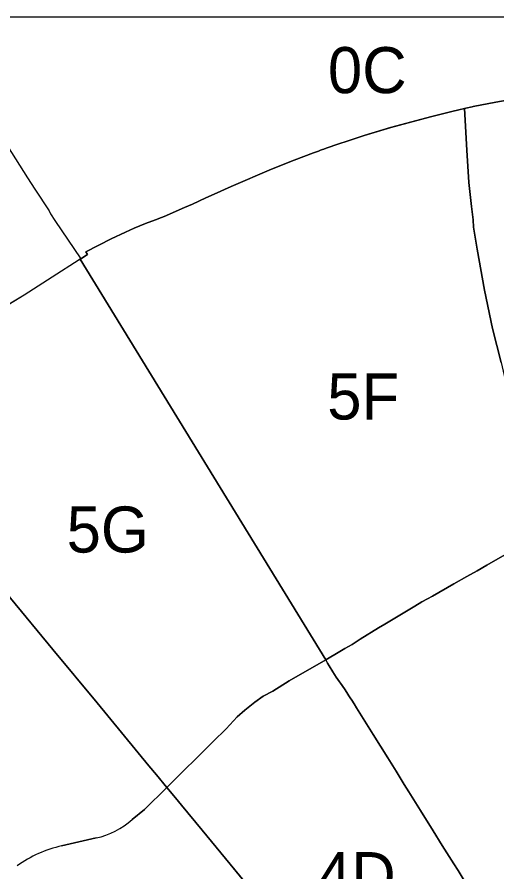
# Model space of a CAD drawing. Extents: x 152750 to 166250, y 378996 to 390000.
# Drawn here: x 157492 to 159576, y 386288 to 390000 of the extents above; entities that cross this region are included whole.
import ezdxf

# ---------------------------------------------------------------- set-up
doc = ezdxf.new("R2010")
doc.units = 0
doc.layers.add('BLT_Nummers', color=7, linetype='Continuous')
doc.layers.add('BLT_Shapes', color=7, linetype='Continuous')

msp = doc.modelspace()

# ---------------------------------------------------------------- linework, layer by layer
at = {"layer": 'BLT_Shapes'}
for p, q in [((163502.8, 390000), (157101, 390000)), ((159473.5, 389611.2), (159571.7, 389630.9)), ((159571.7, 389630.9), (159473.5, 389611.2)), ((159571.7, 389630.9), (159670.9, 389648.8)), ((159670.9, 389648.8), (159571.7, 389630.9)), ((159435.7, 389602.7), (159410.2, 389597)), ((159441.2, 389603.9), (159435.7, 389602.7)), ((159441.2, 389603.9), (159468.8, 389610.2)), ((159468.8, 389610.2), (159441.2, 389603.9)), ((159468.8, 389610.2), (159473.5, 389611.2)), ((159473.5, 389611.2), (159468.8, 389610.2)), ((158834.6, 389430.4), (158824.5, 389426.8)), ((158695.6, 389379.1), (158597.2, 389339.9)), ((158597.2, 389339.9), (158422.3, 389264.6)), ((159455, 389268.9), (159454.2, 389281.4)), ((159465.3, 389176.8), (159455, 389268.9)), ((158312.2, 389214.6), (158253.9, 389188.2)), ((158219.7, 389173.3), (158131.1, 389134.8)), ((158253.9, 389188.2), (158219.7, 389173.3)), ((159473.4, 389120), (159465.3, 389176.8)), ((159473.9, 389088.3), (159473.4, 389120)), ((159489.7, 388991.7), (159473.9, 389088.3)), ((157765.5, 388948.2), (157741.5, 388932.9)), ((157768.1, 388949.9), (157765.5, 388948.2)), ((157765.5, 388948.2), (158832.4, 387209.5)), ((158832.4, 387209.5), (157765.5, 388948.2)), ((157793.5, 388966.1), (157768.1, 388949.9)), ((157521.8, 388792.8), (157405.1, 388721.9)), ((159532.8, 387620.6), (159610.8, 387665.5)), ((159219, 387441.9), (159250.2, 387460.1)), ((159250.2, 387460.1), (159274.2, 387473.7)), ((158946.8, 387276.1), (158982.2, 387298)), ((158674.2, 387117.6), (158832.4, 387209.5)), ((158832.4, 387209.5), (158840.8, 387194.7)), ((158602.5, 387073.4), (158674.2, 387117.6)), ((158884.5, 387123.4), (158903.3, 387098.1)), ((158928.7, 387059.6), (158933, 387052.1)), ((158933, 387052.1), (158938.8, 387043.7)), ((158481.7, 386989.7), (158524.8, 387025.5)), ((158938.8, 387043.7), (158945.3, 387033.3)), ((158448.3, 386961), (158481.7, 386989.7)), ((158400.4, 386909.6), (158448.3, 386961)), ((158343.1, 386854.5), (158400.4, 386909.6)), ((159038, 386885.3), (159101.8, 386783.2)), ((158142.3, 386654.8), (158343.1, 386854.5)), ((159101.8, 386783.2), (159138.1, 386725)), ((158045.2, 386558.7), (158142.3, 386654.8)), ((158142.3, 386654.8), (158180.1, 386609.2)), ((158180.1, 386609.2), (158142.3, 386654.8)), ((158180.1, 386609.2), (158206.4, 386577.5)), ((158206.4, 386577.5), (158180.1, 386609.2)), ((158296.1, 386469.4), (158206.4, 386577.5)), ((157991.4, 386515.6), (158045.2, 386558.7)), ((159244.4, 386554.7), (159299.6, 386466.5)), ((158417.7, 386321.3), (158296.1, 386469.4)), ((157834.8, 386435.5), (157685.4, 386400.8)), ((157685.4, 386400.8), (157834.8, 386435.5)), ((158559.6, 386149.1), (158417.7, 386321.3))]:
    msp.add_line(p, q, dxfattribs=at)
for points in [[(157101, 390000), (157206, 389831.1), (157337.3, 389621), (157449.6, 389439.9), (157536.9, 389302.4), (157569, 389253.3), (157631.4, 389159.1), (157636.9, 389146.1), (157655.3, 389116.9), (157768.1, 388949.9)], [(157768.1, 388949.9), (157793.5, 388966.1), (157798, 388969), (157790.9, 388980.5), (157899.8, 389036.8), (157962.2, 389065.7), (157981.3, 389074.6), (158000, 389083.3), (158049.7, 389103.9), (158093.6, 389119.1), (158118.7, 389129.4), (158131.1, 389134.8), (158219.7, 389173.3), (158253.9, 389188.2), (158312.2, 389214.6), (158348.4, 389231.1), (158422.3, 389264.6), (158597.2, 389339.9), (158695.6, 389379.1), (158779, 389410.6), (158800.8, 389418.4), (158810.3, 389421.8), (158818.1, 389424.5), (158824.5, 389426.8), (158834.6, 389430.4), (158846.8, 389434.7), (158877.1, 389445.5), (158939.1, 389465.8), (159000, 389485.8), (159115.2, 389520.7), (159287.7, 389567.6), (159379.7, 389590.1), (159410.2, 389597), (159441.2, 389603.9)], [(159410.2, 389597), (159379.7, 389590.1), (159287.7, 389567.6), (159114.2, 389520.4), (159000, 389485.8), (158939.1, 389465.8)], [(159435.7, 389602.7), (159445.7, 389422.8), (159454.2, 389281.4), (159455, 389268.9), (159465.3, 389176.8), (159473.4, 389120), (159473.9, 389088.3), (159489.7, 388991.7), (159522.2, 388814.1), (159556.9, 388647.5), (159594.9, 388500.2), (159612.6, 388424.8), (159641, 388307.4), (159654.7, 388247.3), (159661.5, 388218), (159672.4, 388174.9)], [(159454.2, 389281.4), (159445.7, 389422.8), (159435.7, 389602.7)], [(158939.1, 389465.8), (158877.1, 389445.5), (158846.8, 389434.7), (158834.6, 389430.4)], [(157449.6, 389439.9), (157536.9, 389302.4), (157569, 389253.3), (157631.4, 389159.1), (157636.9, 389146.1), (157655.3, 389116.9), (157768.1, 388949.9), (157741.5, 388932.9), (157663.7, 388883.3), (157521.8, 388792.8), (157405.1, 388721.9)], [(158824.5, 389426.8), (158818.1, 389424.5), (158810.3, 389421.8), (158800.8, 389418.4), (158779, 389410.6), (158695.6, 389379.1)], [(158422.3, 389264.6), (158348.4, 389231.1), (158312.2, 389214.6)], [(158131.1, 389134.8), (158118.7, 389129.4), (158093.6, 389119.1), (158049.7, 389103.9), (158000, 389083.3), (157981.3, 389074.6), (157962.2, 389065.7), (157899.8, 389036.8), (157790.9, 388980.5), (157798, 388969), (157793.5, 388966.1)], [(159594.9, 388500.2), (159556.9, 388647.5), (159522.2, 388814.1), (159489.7, 388991.7)], [(157741.5, 388932.9), (157663.7, 388883.3), (157521.8, 388792.8)], [(156751.8, 388357.8), (156831.4, 388247.5), (156937.4, 388116.5), (157111.7, 387900.3), (157296.6, 387677.3), (157336.2, 387630), (157462.8, 387477), (157647.5, 387253.7), (157839.6, 387022), (158064.5, 386749), (158097.1, 386709.1), (158142.3, 386654.8)], [(159792.8, 387771.2), (159770, 387757.1), (159717.4, 387727.2), (159645.6, 387685.3), (159610.8, 387665.5), (159532.8, 387620.6), (159489.9, 387595.9), (159445.1, 387570.3), (159389.6, 387538.7), (159297, 387485.8), (159274.2, 387473.7), (159250.2, 387460.1), (159219, 387441.9), (159089.4, 387364.2), (159062, 387347.3), (158982.2, 387298), (158946.8, 387276.1), (158916.2, 387258.2), (158893.9, 387244.6), (158832.4, 387209.5)], [(157647.5, 387253.7), (157462.8, 387477), (157336.2, 387630), (157296.6, 387677.3)], [(159389.6, 387538.7), (159445.1, 387570.3), (159489.9, 387595.9), (159532.8, 387620.6)], [(159274.2, 387473.7), (159297, 387485.8), (159389.6, 387538.7)], [(158982.2, 387298), (159062, 387347.3), (159089.4, 387364.2), (159219, 387441.9)], [(158832.4, 387209.5), (158893.9, 387244.6), (158916.2, 387258.2), (158946.8, 387276.1)], [(158142.3, 386654.8), (158097.1, 386709.1), (158064.5, 386749), (157839.6, 387022), (157647.5, 387253.7)], [(158832.4, 387209.5), (158674.2, 387117.6), (158602.5, 387073.4), (158560.6, 387050.7), (158524.8, 387025.5), (158481.7, 386989.7), (158448.3, 386961), (158400.4, 386909.6), (158343.1, 386854.5), (158142.3, 386654.8)], [(159442.8, 386236.3), (159407.4, 386293.5), (159389.6, 386322.5), (159339, 386403.1), (159299.6, 386466.5), (159244.4, 386554.7), (159193.6, 386636), (159173.8, 386667.5), (159138.1, 386725), (159101.8, 386783.2), (159038, 386885.3), (158966.6, 386999.9), (158955.3, 387017.4), (158945.3, 387033.3), (158938.8, 387043.7), (158933, 387052.1), (158928.7, 387059.6), (158916.4, 387078.4), (158903.3, 387098.1), (158884.5, 387123.4), (158877.7, 387134.1), (158863.1, 387157.1), (158846.9, 387183.1), (158840.8, 387194.7), (158832.4, 387209.5)], [(158840.8, 387194.7), (158846.9, 387183.1), (158863.1, 387157.1), (158877.7, 387134.1), (158884.5, 387123.4)], [(158903.3, 387098.1), (158916.4, 387078.4), (158928.7, 387059.6)], [(158524.8, 387025.5), (158560.6, 387050.7), (158602.5, 387073.4)], [(158945.3, 387033.3), (158955.3, 387017.4), (158966.6, 386999.9), (159038, 386885.3)], [(159138.1, 386725), (159173.8, 386667.5), (159193.6, 386636), (159244.4, 386554.7)], [(158142.3, 386654.8), (158045.2, 386558.7), (157991.4, 386515.6)], [(158206.4, 386577.5), (158296.1, 386469.4), (158417.7, 386321.3), (158559.6, 386149.1), (158640.6, 386051.2), (158726.9, 385947.1), (158878.9, 385763.5), (159020.3, 385592.2), (159157.3, 385425.3), (159291.1, 385263.1)], [(159299.6, 386466.5), (159339, 386403.1), (159389.6, 386322.5), (159407.4, 386293.5), (159442.8, 386236.3), (159509.8, 386129.4), (159517.9, 386116.7)]]:
    msp.add_lwpolyline(points, dxfattribs=at)
for centre, radius, start, end in [((157762.4, 386770.1), 342.3, 282.212, 311.9839), ((157762.4, 386770.1), 342.3, 282.212, 311.9839), ((157807.7, 385865.1), 549.5, 102.8548, 125.0896), ((157807.7, 385865.1), 549.5, 102.8548, 125.0896)]:
    msp.add_arc(centre, radius, start, end, dxfattribs=at)

# ---------------------------------------------------------------- texts
at = {"layer": 'BLT_Nummers'}
for s, p in [('0C', (158842.1, 389669.7)), ('5F', (158839.2, 388252.5)), ('5G', (157707, 387674.8)), ('4D', (158794.3, 386174))]:
    msp.add_text(s, height=200, dxfattribs=at).set_placement(p)

doc.saveas('drawing.dxf')
